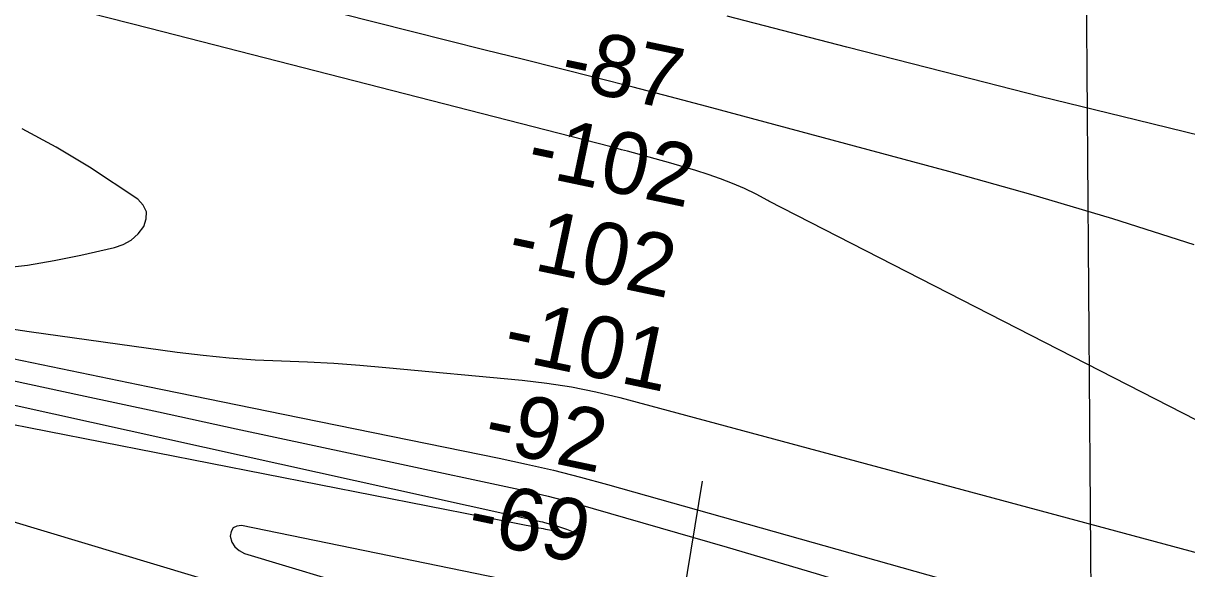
# Model space of a CAD drawing. Extents: x 3535183 to 3573198, y 534952 to 560562.
# Drawn here: x 3559297 to 3560553, y 544470 to 545059 of the extents above; entities that cross this region are included whole.
import ezdxf

# ---------------------------------------------------------------- set-up
doc = ezdxf.new("R2010")
doc.units = 0
for name, color, linetype in [('V-GRID-MAJR', 7, 'Continuous'), ('V-RIVR-RANG', 7, 'Continuous'), ('V-TOPO-MAJR', 7, 'Continuous'), ('V-TOPO-MINR', 7, 'Continuous')]:
    doc.layers.add(name, color=color, linetype=linetype)

msp = doc.modelspace()

# ---------------------------------------------------------------- linework, layer by layer
at = {"layer": 'V-GRID-MAJR'}
msp.add_spline([(3560480.4390000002, 540512.311), (3560433.741, 546570.077), (3560387.018, 552630.928), (3560340.296, 558691.794), (3560340.272, 558694.862)], degree=3, dxfattribs=at)
at = {"layer": 'V-RIVR-RANG'}
msp.add_line((3559877.2032, 543636.9873000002), (3560030.606, 544564.3855999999), dxfattribs=at)
at = {"layer": 'V-TOPO-MAJR'}
for points in [[(3561026.2913430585, 544393.5039926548), (3560102.068583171, 544867.2091795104), (3560100.8117545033, 544867.9232650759), (3560088.418815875, 544874.5381173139), (3560075.8208732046, 544880.7045876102), (3560062.915424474, 544886.1984849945), (3560049.8049717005, 544891.2440004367), (3560036.494059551, 544895.8058252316), (3560023.122260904, 544900.1742135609), (3560009.6591325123, 544904.252447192), (3559996.135117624, 544908.1372443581), (3559955.9732040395, 544919.2051140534), (3559949.5563437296, 544920.9555779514), (3559943.1335619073, 544922.6838053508), (3559936.7018978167, 544924.3786780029), (3559930.2643122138, 544926.051314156), (3559433.82744361, 545053.6630849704), (3559324.8553322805, 545081.4600750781)], [(3559200.465583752, 544741.771725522), (3559303.4111850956, 544726.3115198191), (3559463.3014864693, 544704.0272395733), (3559491.3484137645, 544700.5817764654), (3559519.4468623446, 544697.7456283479), (3559547.622592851, 544695.8234527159), (3559575.8498446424, 544694.5105920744), (3559604.0993206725, 544693.38880283), (3559632.326800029, 544691.9112658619), (3559660.5212843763, 544689.9001073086), (3559688.6937720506, 544687.5332010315), (3559835.924155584, 544673.7600784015), (3559862.5303618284, 544670.5858256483), (3559888.975823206, 544666.5183428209), (3559915.180167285, 544661.1110148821), (3559941.2237664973, 544654.8104568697), (3560661.0174079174, 544461.1470417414)]]:
    msp.add_lwpolyline(points, dxfattribs=at)
at = {"layer": 'V-TOPO-MINR'}
for points in [[(3560561.1055009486, 544819.7600690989), (3560473.367942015, 544848.0700312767), (3560384.9995730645, 544874.3448210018), (3560296.210664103, 544899.2628290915), (3560035.238106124, 544969.2594221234), (3559995.46273511, 544979.810465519), (3559955.649577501, 544990.215277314), (3559915.77974, 545000.4007417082), (3559875.8721159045, 545010.4399745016), (3559875.833930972, 545010.4494686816), (3559835.8850555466, 545020.4084183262), (3559795.9444241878, 545030.4002360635), (3559756.016158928, 545040.4413559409), (3559716.0961377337, 545050.5153439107), (3559563.4711648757, 545089.1311372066)], [(3561333.789609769, 544760.7336754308), (3561252.704927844, 544778.1962168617), (3561171.6308462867, 544795.7080888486), (3561070.4827990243, 544817.6042112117), (3561040.0157222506, 544824.3143020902), (3561009.582015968, 544831.1700849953), (3560979.198365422, 544838.2444059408), (3560948.8480853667, 544845.4644189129), (3560603.638705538, 544928.8979097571), (3560499.1586331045, 544954.4241395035), (3560394.764988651, 544980.2954472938), (3560290.5009861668, 545006.68437215), (3560186.3234116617, 545033.4183750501), (3560057.147685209, 545066.9091620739)], [(3559272.828299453, 544794.7196480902), (3559301.8017582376, 544798.0702444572), (3559330.5705918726, 544802.8704549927), (3559359.203008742, 544808.6370749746), (3559395.6602664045, 544816.9377480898), (3559405.184121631, 544820.371699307), (3559413.799043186, 544825.0790847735), (3559421.050564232, 544831.696621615), (3559427.3931516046, 544839.5875927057), (3559429.9766273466, 544847.9149779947), (3559430.15800484, 544855.7170031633), (3559426.73623496, 544862.7309881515), (3559420.9123668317, 544869.2196130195), (3559368.5492313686, 544903.9248693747), (3559332.8155252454, 544925.5697696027), (3559296.101943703, 544945.1869195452)], [(3558702.889675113, 544799.1015565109), (3559358.87437687, 544657.5295749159), (3559443.0251747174, 544639.3829313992), (3559527.179933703, 544621.2546909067), (3559611.340634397, 544603.1540549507), (3559695.50529623, 544585.0718220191), (3559833.354978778, 544555.4793605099), (3559848.558710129, 544552.0514448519), (3559863.7104124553, 544548.4161117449), (3559878.784071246, 544544.4696524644), (3559893.805701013, 544540.315775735), (3560056.9119050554, 544493.3998404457), (3560153.212504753, 544464.8881199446), (3560249.1998501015, 544435.3847396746), (3560344.7173139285, 544404.393869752), (3560439.921523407, 544372.4113400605), (3560853.0260221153, 544230.0541147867)], [(3558676.119822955, 544782.2332776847), (3559818.2882697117, 544529.4106617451), (3559824.8748473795, 544527.9469332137), (3559831.4597816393, 544526.4758769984), (3559838.0422507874, 544524.993829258), (3559844.623076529, 544523.504453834), (3559855.7136548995, 544520.9846952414), (3559857.7747017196, 544520.485343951), (3559859.820632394, 544519.9272817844), (3559872.7508344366, 544516.2009782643), (3559878.279406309, 544514.4955284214), (3559883.759745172, 544512.654867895), (3559889.167734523, 544510.6113913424), (3559894.5274908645, 544508.4327041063), (3559895.0843002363, 544507.6202105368), (3559895.219900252, 544506.9374315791), (3559894.723686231, 544506.4492245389), (3559893.8062628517, 544506.0907321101), (3559861.310133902, 544512.4334223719), (3559858.7900264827, 544512.9258641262), (3559856.2700599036, 544513.4190247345), (3559853.7503045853, 544513.9132636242), (3559851.230690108, 544514.4082213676), (3559029.559415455, 544676.0014449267)], [(3559285.5806002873, 544696.9772406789), (3559431.609970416, 544666.82994946), (3559577.683912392, 544636.8973619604), (3559810.873626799, 544589.381476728), (3559840.307012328, 544583.0418590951), (3559869.635014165, 544576.268070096), (3559898.804940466, 544568.8430240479), (3559927.8694830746, 544560.983806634), (3560549.4782112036, 544385.4471028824), (3560608.0625148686, 544368.9140369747), (3560666.6505122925, 544352.3940794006), (3560725.2440503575, 544335.8937843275), (3560783.8412821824, 544319.4065975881), (3560884.248133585, 544291.1738446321), (3560892.665169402, 544288.8959601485), (3560901.1094601, 544286.7287697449), (3560909.5946331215, 544284.727620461), (3560918.1070610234, 544282.8371652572), (3561459.4744165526, 544168.1695222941)], [(3559038.125099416, 544595.661386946), (3559763.2243565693, 544377.2953863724), (3559793.429376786, 544368.7068544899), (3559823.7889484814, 544360.7473565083), (3559854.3803473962, 544353.7314093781), (3559885.126297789, 544347.3444961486), (3560167.739025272, 544293.1875845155), (3560285.764754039, 544270.9247684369), (3560403.8734139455, 544249.1185372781), (3560522.106470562, 544227.9971834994), (3560640.4224583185, 544207.3324146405), (3560817.6173638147, 544176.9128869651), (3560847.367862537, 544171.6412892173), (3560877.078052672, 544166.1576704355), (3560906.7277799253, 544160.3560201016), (3560936.3371985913, 544154.3423487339), (3561161.7459808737, 544107.302929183), (3561304.097655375, 544077.950324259), (3561446.5401306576, 544049.0508078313)], [(3559523.750733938, 544514.0274668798), (3559521.5237678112, 544510.1955955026), (3559520.476567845, 544505.0862374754), (3559522.4653976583, 544498.8022765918), (3559525.559899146, 544493.4509199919), (3559530.3129081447, 544489.4984698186), (3559536.171588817, 544486.4786239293), (3559808.9365033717, 544404.3353640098)], [(3559811.1320903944, 544459.4335467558), (3559532.923730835, 544516.5812630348), (3559527.747349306, 544515.9431082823), (3559523.750733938, 544514.0274668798)]]:
    msp.add_lwpolyline(points, dxfattribs=at)

# ---------------------------------------------------------------- texts
at = {"layer": 'V-RIVR-RANG'}
for s, p in [('-87', (3559874.379952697, 544991.5814162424)), ('-102', (3559838.566899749, 544896.9291585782)), ('-102', (3559817.723899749, 544799.1261585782)), ('-101', (3559813.14256071, 544697.8987143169)), ('-92', (3559792.042439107, 544600.1490547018)), ('-69', (3559774.0387767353, 544501.7473104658))]:
    msp.add_text(s, height=67.00000000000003, rotation=348.1115555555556, dxfattribs=at).set_placement(p)

doc.saveas('drawing.dxf')
